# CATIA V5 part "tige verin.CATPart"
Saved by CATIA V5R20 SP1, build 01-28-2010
Part number: tige verin
Bounding box of the stored display mesh (mm): x 190.014 to 309.986, y 347.017 to 880, z 170 to 606.854
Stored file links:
  C:\Users\Nicolas\Documents\Ifma\2A\S3\iao\projet\tige verin.CATPart
  C:\Users\Nicolas\Documents\Ifma\2A\S3\iao\projet\Product1.CATProduct
  C:\Users\Nicolas\Documents\Ifma\2A\S3\iao\projet\corps verin.CATPart
  C:\Users\Nicolas\Documents\Ifma\2A\S3\iao\projet\triangle.CATPart
  C:\Users\Nicolas\Documents\Ifma\2A\S3\iao\projet\bielle2.CATPart
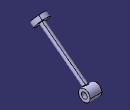
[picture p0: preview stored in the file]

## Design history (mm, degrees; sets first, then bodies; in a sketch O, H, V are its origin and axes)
Set1
  Plane1: linked copy from another document
  DatumCurve1: linked copy from another document
  Plane2: linked copy from another document
  Plane3: linked copy from another document
  Point1: linked copy from another document
  Point2: linked copy from another document
Body1 (main body)
  Sketch1 on Plane1, origin (250, 0, 0), H (0, 1, 0), V (0, 0, 1)
    circle A1 centre (830, 220) radius 50
    reference projected circle E1 centre (830, 220) radius 50 from edge of DatumCurve1
    coincidence: A1 E1
  Pad1: profile Sketch1, direction (1, 0, 0), up to Plane2, opposite side up to Plane3
  Sketch2 on Plane1, origin (250, 0, 0), H (0, 1, 0), V (0, 0, 1)
    construction line L1 (830, 220) -> (0, 850)
    point P1 (830, 220)
    point P2 (0, 850)
    reference projected point E1 (0, 850) from Point1
    reference projected point E2 (830, 220) from Point2
    point P3 (805.5903, 263.6367)
    line L2 (805.5903, 263.6367) -> (793.4983, 247.7061)
    point P4 (793.4983, 247.7061)
    line L3 (793.4983, 247.7061) -> (383.2844, 559.0733)
    line L4 (383.2844, 559.0733) -> (419.5602, 606.8652)
    line L5 (419.5602, 606.8652) -> (451.4215, 582.6813)
    line L6 (451.4215, 582.6813) -> (427.2376, 550.8201)
    line L7 (427.2376, 550.8201) -> (805.5903, 263.6367)
    reference projected circle E3 centre (830, 220) radius 50 from edge [face of Pad1 from Sketch1.A1 | start face of Pad1]
    length L4 = 60
    distance L6 L4 = 40
    distance L7 L3 = 20
    length L7 = 475
    coincidence: P2 E1, P1 E2, P4 L1, P3 E3
    perpendicularity: L2 L1
    parallelism: L3 L1, L4 L2, L5 L1
  Shaft1: profile Sketch2, axis Sketch2.L3, angle 360
  Sketch3 on start face of Pad1, origin (300, 750, 100), H (0, 1, 0), V (0, 0, 1)
    point P1 (80, 120)
    reference projected point E1 (80, 120) from Point2
    coincidence: E1 P1
  Hole1: placed by Sketch3, at (300, 830, 220) direction (-1, 0, 0), diameter 50, through (limit type 3)
  Fillet1: radius 5, on edge [face of Pad1 from Sketch1.A1 | face of Shaft1 from Sketch2.L7]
